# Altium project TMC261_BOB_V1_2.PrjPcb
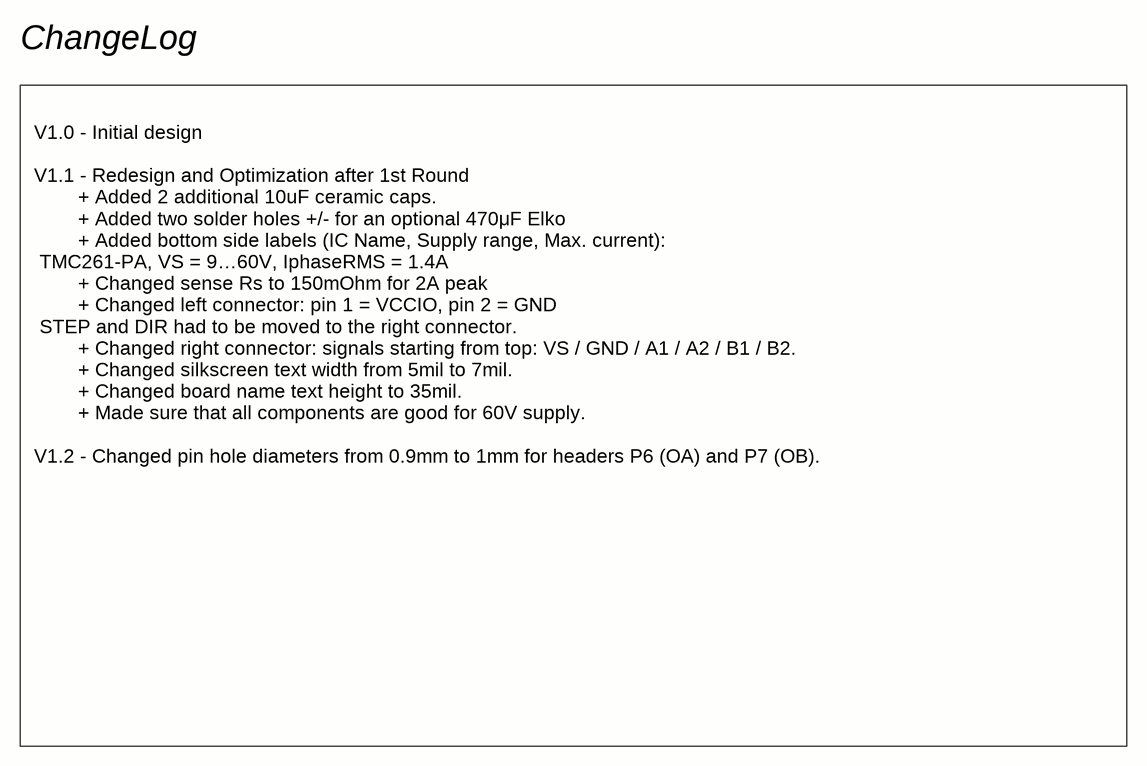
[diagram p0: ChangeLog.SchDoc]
BoardName: TMC261_BOB; BoardVersion: 1.2; Chip: TMC261-PA; IRMS: 1.4A; VS: 9…60V
2 sheets, 27 parts. Net scope: global (net labels, ports and power ports of the same name join across sheets).
Board file: TMC261_BOB_V1_2.PcbDoc
Sheets:
  ChangeLog.SchDoc
  TMC261_BOB_V1_2.SchDoc

## Sheet ChangeLog.SchDoc
size A4

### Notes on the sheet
- ChangeLog
- V1.0 - Initial design
  V1.1 - Redesign and Optimization after 1st Round
  + Added 2 additional 10uF ceramic caps.
  + Added two solder holes +/- for an optional 470μF Elko
  + Added bottom side labels (IC Name, Supply range, Max. current):
  TMC261-PA, VS = 9…60V, IphaseRMS = 1.4A
  + Changed sense Rs to 150mOhm for 2A peak
  + Changed left connector: pin 1 = VCCIO, pin 2 = GND
  STEP and DIR had to be moved to the right connector.
  + Changed right connector: signals starting from top: VS / GND / A1 / A2 / B1 / B2.
  + Changed silkscreen text width from 5mil to 7mil.
  + Changed board name text height to 35mil.
  + Made sure that all components are good for 60V supply.
  V1.2 - Changed pin hole diameters from 0.9mm to 1mm for headers P6 (OA) and P7 (OB).

## Sheet TMC261_BOB_V1_2.SchDoc
size A4
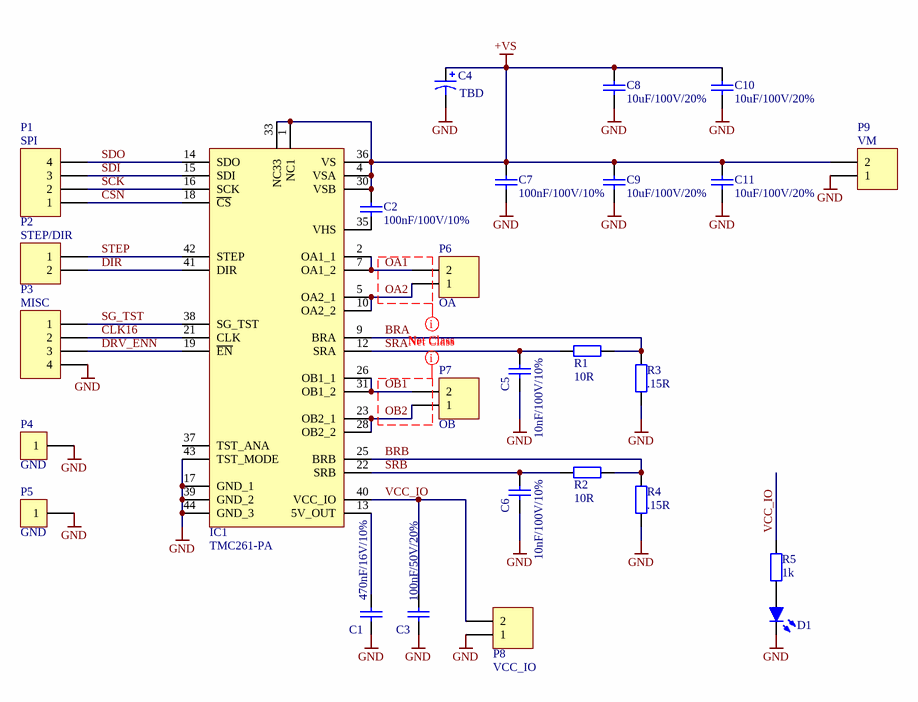
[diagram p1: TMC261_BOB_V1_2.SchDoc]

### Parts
C1  470nF/16V/10%  [C0603]
C2  100nF/100V/10%  [C0603]
C3  100nF/50V/20%  [C0603]
C4  value TBD  [EXT_POL_CAP_FLIPPED]  (hidden comment: Cap Pol1)
C5  10nF/100V/10%  [C0603]
C6  10nF/100V/10%  [C0603]
C7  100nF/100V/10%  [C0603]
C8  10uF/100V/20%  [CKG45NX7S2A106M500JH]
C9  10uF/100V/20%  [CKG45NX7S2A106M500JH]
C10  10uF/100V/20%  [CKG45NX7S2A106M500JH]
C11  10uF/100V/20%  [CKG45NX7S2A106M500JH]
D1  LED, Blue, SMD, 20mA, 2.8V, 465 nm  [LED_0603]  (value not drawn)
IC1  value TMC261-PA  [TMC26x_PQFP44_0.8_10X10_TMC236]  (hidden comment: TMC261)
P1  SPI  [4_PIN_THT]
P2  STEP/DIR  [2_PIN_THT]
P3  MISC  [4_PIN_THT]
P4  GND  [TH_PIN]
P5  GND  [TH_PIN]
P6  OA  [2_PIN_THT_1MM_HOLE]
P7  OB  [2_PIN_THT_1MM_HOLE]
P8  VCC_IO  [2_PIN_THT]
P9  VM  [2_PIN_THT]
R1  Resistance: 10R  [R0603]  (hidden comment: 10R / 100mW / 1%)
R2  Resistance: 10R  [R0603]  (hidden comment: 10R / 100mW / 1%)
R3  Resistance: .15R  [R1210]  (hidden comment: .15R / 1W / 1%)
R4  Resistance: .15R  [R1210]  (hidden comment: .15R / 1W / 1%)
R5  1k  [R0603]

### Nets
+VS: C2.2 C4.1 C7.2 C8.2 C9.2 C10.2 C11.2 IC1.1(NC1) IC1.4(VSA) IC1.30(VSB) IC1.33(NC33) IC1.36(VS) P9.2
GND: C1.2 C3.1 C4.2 C5.1 C6.1 C7.1 C8.1 C9.1 C10.1 C11.1 D1.2(K) IC1.17(GND_1) IC1.39(GND_2) IC1.43(TST_MODE) IC1.44(GND_3) P3.4 P4.1 P5.1 P8.1 P9.1 R3.1 R4.1
BRA: IC1.9(BRA) R1.1 R3.2
BRB: IC1.25(BRB) R2.1 R4.2
CLK16: IC1.21(CLK) P3.2
CSN: IC1.18(~{CS}) P1.1
DIR: IC1.41(DIR) P2.2
DRV_ENN: IC1.19(~{EN}) P3.3
OA1: IC1.2(OA1_1) IC1.7(OA1_2) P6.2
OA2: IC1.5(OA2_1) IC1.10(OA2_2) P6.1
OB1: IC1.26(OB1_1) IC1.31(OB1_2) P7.2
OB2: IC1.23(OB2_1) IC1.28(OB2_2) P7.1
SCK: IC1.16(SCK) P1.2
SDI: IC1.15(SDI) P1.3
SDO: IC1.14(SDO) P1.4
SG_TST: IC1.38(SG_TST) P3.1
SRA: C5.2 IC1.12(SRA) R1.2
SRB: C6.2 IC1.22(SRB) R2.2
STEP: IC1.42(STEP) P2.1
VCC_IO: C3.2 IC1.40(VCC_IO) P8.2 R5.1
NetC1_1: C1.1 IC1.13(5V_OUT)
NetC2_1: C2.1 IC1.35(VHS)
NetD1_1: D1.1(A) R5.2

Not connected (* = marked no-connect by the designer): IC1 37(TST_ANA)

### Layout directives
net class MotorOutput: OA1, OA2, OB1, OB2

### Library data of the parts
C1 = Capacitor: Ceramic capacitor; MPN: MC0603X474K160CT; Type: MLCC; VoltageRating: 16V; ComponentLinknDescription: Datasheet; MF: Multicomp; Capacitance: 470nF; Precision: 10%
C2 C7 = 0.1 µF, 100 V, ± 10%, X7R, GRM Series: SMD Multilayer Ceramic Capacitor, 0603 [1608 Metric], 0.1 µF, 100 V, ± 10%, X7R, GRM Series; MPN: GRM188R72A104KA35D; Type: MLCC; VoltageRating: 100V; ComponentLinknDescription: Datasheet; MF: MURATA; Capacitance: 100nF
C3 = Capacitor: Ceramic capacitor; MPN: MC0603F104M500CT; Type: MLCC; VoltageRating: 50V; ComponentLinknDescription: Datasheet; MF: Multicomp; Capacitance: 100nF; Precision: 20%
C4 = Cap Pol1: Polarized Capacitor (Radial)
C5 C6 = SMD Multilayer Ceramic Capacitor, 0603 [1608 Metric], 0.01 µF, 100 V, ± 10%, X7R, MC Series: Ceramic capacitor; MPN: MC0603B103K101CT; Type: MLCC; VoltageRating: 100V; MF: MULTICOMP; Precision: 10%; Capacitance: 10nF
C8-C11 = 10 µF, 100 V, ± 20%, X7S, CKG Series: SMD Multilayer Ceramic Capacitor, 1812 [4532 Metric], 10 µF, 100 V, ± 20%, X7S, CKG Series; Type: MLCC; VoltageRating: 100V; ComponentLinknDescription: Datasheet; MF: TDK; Capacitance: 10uF
D1 = LED, Blue, SMD, 20mA, 2.8V, 465 nm: MPN: LTST-C191TBKT-5A; MF: Lite-On
IC1 = TMC261-PA: coolStep™ driver with Step/Dir Interface and SPI, up to 30V,  internal MOSFET for up to 4 A, PQFP-44; Manufacturer: TRINAMIC; Ordercode - Distri#1: 1460-1043-ND; Geometry.Height: 1,6mm
P1 P3 = Header 4: Header, 4-Pin; Fitted: Not fitted
P2 P6-P9 = Header 2: Header, 2-Pin; Fitted: Not fitted
P4 P5 = PIN: Note: n.b; Fitted: Not fitted
R1 R2 = RES SMD 10 OHM 75V 1% 0603: 0.1 Ohm ±1% 1W Chip Resistor 1210 (3225 Metric) Automotive AEC-Q200, Current Sense, Moisture Resistant Thick Film; MPN: MCMR06X10R0FTL; VoltageRating: 75V; Temp coefficient: *ppm; MF: MULTICOMP
R3 R4 = RES SMD 0.15 OHM 1% 1W 1210: 0.15 Ohm ±1% 1W Chip Resistor 1210 (3225 Metric) Automotive AEC-Q200, Current Sense, Moisture Resistant Thick Film; MPN: RCWE1210R150FKEA; VoltageRating: 50V; Temp coefficient: *ppm; MF: Vishay
R5 = 1 kohm, 50 V, 0603 [1608 Metric], 63 mW, ± 1%, MC Series: MPN: MC0063W060311K; VoltageRating: 50V; Temp coefficient: *ppm; PowerRating: 63mW; MF: MULTICOMP

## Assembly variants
TMC261_BOB_V1.1: not fitted C4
